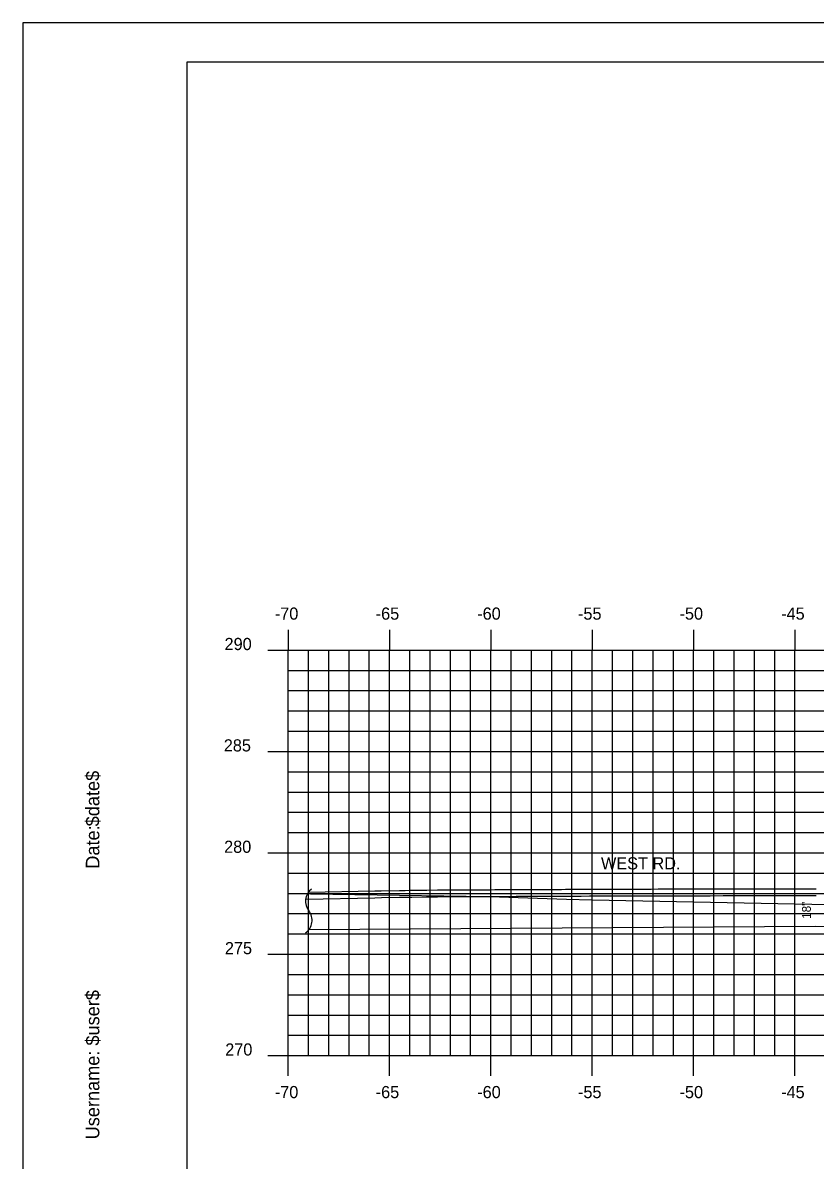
# Model space of a CAD drawing. Extents: x 853563 to 853733, y 366268 to 366378.
# Drawn here: x 853562.7 to 853601.8, y 366322.1 to 366378.2 of the extents above; entities that cross this region are included whole.
import ezdxf

# ---------------------------------------------------------------- set-up
doc = ezdxf.new("R2010")
doc.units = 0
for name, color, linetype in [('ANNOTATION', 7, 'Continuous'), ('BORDER', 7, 'Continuous'), ('D_Roadway_Edge_TW', 7, 'Continuous'), ('D_Roadway_SubGrade', 7, 'Continuous'), ('D_Text_Standard', 7, 'Continuous'), ('H_V ANNOTATION', 7, 'Continuous'), ('MAJOR', 7, 'Continuous'), ('MINOR', 7, 'Continuous'), ('PLOT BOUNDARY', 7, 'Continuous'), ('S_Roadway_Centerline', 7, 'Continuous')]:
    doc.layers.add(name, color=color, linetype=linetype)

msp = doc.modelspace()

# ---------------------------------------------------------------- linework, layer by layer
at = {"layer": 'BORDER'}
for p, q in [((853730.768, 366376.236), (853570.768, 366376.236)), ((853570.768, 366376.236), (853570.768, 366271.236))]:
    msp.add_line(p, q, dxfattribs=at)
at = {"layer": 'D_Roadway_Edge_TW'}
for points in [[(853576.768, 366335.291), (853580.042, 366335.354), (853580.361, 366335.36), (853581.26, 366335.377), (853581.487, 366335.381), (853581.532, 366335.382), (853581.769, 366335.387), (853581.863, 366335.388), (853582.591, 366335.401), (853582.613, 366335.402), (853582.614, 366335.402), (853582.615, 366335.402), (853583.136, 366335.405), (853583.505, 366335.407), (853583.521, 366335.407), (853583.564, 366335.407), (853584.465, 366335.412), (853585.346, 366335.417), (853585.473, 366335.418), (853585.477, 366335.418), (853585.505, 366335.418), (853585.723, 366335.419), (853585.759, 366335.419), (853585.957, 366335.42), (853587.02, 366335.425), (853587.089, 366335.426), (853587.351, 366335.427), (853587.553, 366335.428), (853588.237, 366335.431), (853588.247, 366335.431), (853588.251, 366335.431), (853588.901, 366335.434), (853589.162, 366335.435), (853589.25, 366335.435), (853589.453, 366335.436), (853590.225, 366335.439), (853590.629, 366335.441), (853590.703, 366335.441), (853590.832, 366335.442), (853590.862, 366335.442), (853590.913, 366335.442), (853591.437, 366335.444), (853591.78, 366335.445), (853592.137, 366335.446), (853592.611, 366335.448), (853592.746, 366335.448), (853592.908, 366335.448), (853593.097, 366335.449), (853593.311, 366335.45), (853593.67, 366335.451), (853594.015, 366335.452), (853594.136, 366335.452), (853594.261, 366335.452), (853594.711, 366335.454), (853595.103, 366335.454), (853595.433, 366335.455), (853595.691, 366335.455), (853595.766, 366335.455), (853595.868, 366335.455), (853596.045, 366335.455), (853596.172, 366335.455), (853596.59, 366335.455), (853597.224, 366335.457), (853597.358, 366335.457), (853597.436, 366335.457), (853597.634, 366335.457), (853597.987, 366335.457), (853598.168, 366335.458), (853598.26, 366335.458), (853598.744, 366335.459), (853598.97, 366335.458), (853599.067, 366335.458), (853599.282, 366335.459), (853599.953, 366335.46), (853600.212, 366335.459), (853600.27, 366335.459), (853600.291, 366335.459), (853600.34, 366335.459), (853600.474, 366335.46), (853601.089, 366335.46), (853601.288, 366335.46), (853601.69, 366335.461), (853601.808, 366335.46)], [(853576.632, 366334.955), (853580.049, 366335.021), (853580.367, 366335.027), (853581.267, 366335.044), (853581.493, 366335.048), (853581.539, 366335.049), (853581.775, 366335.054), (853581.869, 366335.055), (853582.595, 366335.068), (853582.615, 366335.069), (853582.616, 366335.069), (853582.616, 366335.069), (853583.138, 366335.072), (853583.507, 366335.074), (853583.523, 366335.074), (853583.566, 366335.074), (853584.467, 366335.079), (853585.348, 366335.084), (853585.474, 366335.085), (853585.479, 366335.085), (853585.724, 366335.086), (853585.761, 366335.086), (853585.958, 366335.087), (853587.022, 366335.092), (853587.09, 366335.093), (853587.352, 366335.094), (853587.555, 366335.095), (853588.238, 366335.098), (853588.249, 366335.098), (853588.252, 366335.098), (853588.903, 366335.101), (853589.163, 366335.102), (853589.252, 366335.102), (853589.455, 366335.103), (853590.227, 366335.106), (853590.63, 366335.108), (853590.705, 366335.108), (853590.833, 366335.109), (853590.863, 366335.109), (853590.914, 366335.109), (853591.781, 366335.112), (853592.138, 366335.113), (853592.612, 366335.115), (853592.747, 366335.115), (853593.098, 366335.116), (853593.312, 366335.117), (853593.671, 366335.118), (853594.016, 366335.119), (853594.137, 366335.119), (853594.262, 366335.119), (853594.711, 366335.121), (853595.103, 366335.121), (853595.434, 366335.122), (853595.691, 366335.122), (853595.767, 366335.122), (853595.868, 366335.122), (853596.046, 366335.122), (853596.172, 366335.122), (853596.59, 366335.122), (853597.225, 366335.124), (853597.358, 366335.124), (853597.436, 366335.124), (853597.634, 366335.124), (853597.988, 366335.124), (853598.168, 366335.125), (853598.261, 366335.125), (853598.744, 366335.126), (853598.97, 366335.125), (853599.067, 366335.125), (853599.283, 366335.126), (853599.953, 366335.127), (853600.212, 366335.126), (853600.27, 366335.126), (853600.291, 366335.126), (853600.34, 366335.126), (853600.475, 366335.127), (853601.089, 366335.127), (853601.288, 366335.127), (853601.69, 366335.128), (853601.808, 366335.127)]]:
    msp.add_lwpolyline(points, dxfattribs=at)
for centre, start, end in [((853577.387, 366334.844), 127.9752, 217.9752), ((853576.183, 366333.904), 305.7646, 37.9752)]:
    msp.add_arc(centre, 0.764, start, end, dxfattribs=at)
at = {"layer": 'D_Roadway_SubGrade'}
msp.add_lwpolyline([(853576.803, 366333.458), (853601.768, 366333.627), (853626.771, 366333.22)], dxfattribs=at)
at = {"layer": 'MAJOR'}
for p, q in [((853575.768, 366348.238), (853575.768, 366347.236)), ((853580.768, 366348.238), (853580.768, 366347.236)), ((853585.768, 366348.238), (853585.768, 366347.236)), ((853590.768, 366348.238), (853590.768, 366347.236)), ((853595.768, 366348.238), (853595.768, 366347.236)), ((853600.768, 366348.238), (853600.768, 366347.236)), ((853574.766, 366347.236), (853575.768, 366347.236)), ((853575.768, 366347.236), (853715.768, 366347.236)), ((853575.768, 366327.236), (853575.768, 366347.236)), ((853575.768, 366327.236), (853575.768, 366347.236)), ((853575.768, 366347.236), (853715.768, 366347.236)), ((853580.768, 366327.236), (853580.768, 366347.236)), ((853585.768, 366327.236), (853585.768, 366347.236)), ((853590.768, 366327.236), (853590.768, 366347.236)), ((853595.768, 366327.236), (853595.768, 366347.236)), ((853600.768, 366327.236), (853600.768, 366347.236)), ((853574.766, 366342.236), (853575.768, 366342.236)), ((853575.768, 366342.236), (853715.768, 366342.236)), ((853574.766, 366337.236), (853575.768, 366337.236)), ((853575.768, 366337.236), (853715.768, 366337.236)), ((853574.766, 366332.236), (853575.768, 366332.236)), ((853575.768, 366332.236), (853715.768, 366332.236)), ((853574.766, 366327.236), (853575.768, 366327.236)), ((853575.768, 366327.236), (853715.768, 366327.236)), ((853575.768, 366327.236), (853715.768, 366327.236)), ((853575.768, 366326.234), (853575.768, 366327.236)), ((853580.768, 366326.234), (853580.768, 366327.236)), ((853585.768, 366326.234), (853585.768, 366327.236)), ((853590.768, 366326.234), (853590.768, 366327.236)), ((853595.768, 366326.234), (853595.768, 366327.236)), ((853600.768, 366326.234), (853600.768, 366327.236))]:
    msp.add_line(p, q, dxfattribs=at)
at = {"layer": 'MINOR'}
for p, q in [((853576.768, 366327.236), (853576.768, 366347.236)), ((853577.768, 366327.236), (853577.768, 366347.236)), ((853578.768, 366327.236), (853578.768, 366347.236)), ((853579.768, 366327.236), (853579.768, 366347.236)), ((853581.768, 366327.236), (853581.768, 366347.236)), ((853582.768, 366327.236), (853582.768, 366347.236)), ((853583.768, 366327.236), (853583.768, 366347.236)), ((853584.768, 366327.236), (853584.768, 366347.236)), ((853586.768, 366327.236), (853586.768, 366347.236)), ((853587.768, 366327.236), (853587.768, 366347.236)), ((853588.768, 366327.236), (853588.768, 366347.236)), ((853589.768, 366327.236), (853589.768, 366347.236)), ((853591.768, 366327.236), (853591.768, 366347.236)), ((853592.768, 366327.236), (853592.768, 366347.236)), ((853593.768, 366327.236), (853593.768, 366347.236)), ((853594.768, 366327.236), (853594.768, 366347.236)), ((853596.768, 366327.236), (853596.768, 366347.236)), ((853597.768, 366327.236), (853597.768, 366347.236)), ((853598.768, 366327.236), (853598.768, 366347.236)), ((853599.768, 366327.236), (853599.768, 366347.236)), ((853575.768, 366346.236), (853715.768, 366346.236)), ((853575.768, 366346.236), (853576.77, 366346.236)), ((853575.768, 366345.236), (853715.768, 366345.236)), ((853575.768, 366345.236), (853576.77, 366345.236)), ((853575.768, 366344.236), (853715.768, 366344.236)), ((853575.768, 366344.236), (853576.77, 366344.236)), ((853575.768, 366343.236), (853715.768, 366343.236)), ((853575.768, 366343.236), (853576.77, 366343.236)), ((853575.768, 366341.236), (853715.768, 366341.236)), ((853575.768, 366341.236), (853576.77, 366341.236)), ((853575.768, 366340.236), (853715.768, 366340.236)), ((853575.768, 366340.236), (853576.77, 366340.236)), ((853575.768, 366339.236), (853715.768, 366339.236)), ((853575.768, 366339.236), (853576.77, 366339.236)), ((853575.768, 366338.236), (853715.768, 366338.236)), ((853575.768, 366338.236), (853576.77, 366338.236)), ((853575.768, 366336.236), (853715.768, 366336.236)), ((853575.768, 366336.236), (853576.77, 366336.236)), ((853575.768, 366335.236), (853715.768, 366335.236)), ((853575.768, 366335.236), (853576.77, 366335.236)), ((853575.768, 366334.236), (853715.768, 366334.236)), ((853575.768, 366334.236), (853576.77, 366334.236)), ((853575.768, 366333.236), (853715.768, 366333.236)), ((853575.768, 366333.236), (853576.77, 366333.236)), ((853575.768, 366331.236), (853715.768, 366331.236)), ((853575.768, 366331.236), (853576.77, 366331.236)), ((853575.768, 366330.236), (853715.768, 366330.236)), ((853575.768, 366330.236), (853576.77, 366330.236)), ((853575.768, 366329.236), (853715.768, 366329.236)), ((853575.768, 366329.236), (853576.77, 366329.236)), ((853575.768, 366328.236), (853715.768, 366328.236)), ((853575.768, 366328.236), (853576.77, 366328.236))]:
    msp.add_line(p, q, dxfattribs=at)
at = {"layer": 'PLOT BOUNDARY'}
msp.add_lwpolyline([(853562.674, 366268.177), (853732.674, 366268.177), (853732.674, 366378.177), (853562.674, 366378.177)], close=True, dxfattribs=at)
at = {"layer": 'S_Roadway_Centerline'}
msp.add_lwpolyline([(853575.768, 366335.23), (853584.553, 366335.101), (853586.197, 366335.061), (853587.12, 366335.034), (853589.489, 366334.954), (853590.768, 366334.911), (853605.767, 366334.615)], dxfattribs=at)

# ---------------------------------------------------------------- texts
at = {"layer": 'ANNOTATION'}
msp.add_text('WEST RD.', height=0.6, dxfattribs=at).set_placement((853591.198, 366336.418))
at = {"layer": 'BORDER'}
for s, p in [('$date$', (853566.453, 366338.542)), ('Date:', (853566.453, 366336.453)), ('$user$', (853566.453, 366327.728)), ('Username:', (853566.453, 366323.104))]:
    msp.add_text(s, height=0.6696, rotation=90, dxfattribs=at).set_placement(p)
at = {"layer": 'D_Text_Standard'}
msp.add_text('18"', height=0.4335, rotation=90, dxfattribs=at).set_placement((853601.55, 366333.977))
at = {"layer": 'H_V ANNOTATION'}
for s, p in [('-70', (853575.109, 366348.736)), ('-65', (853580.085, 366348.736)), ('-60', (853585.093, 366348.736)), ('-55', (853590.064, 366348.736)), ('-50', (853595.072, 366348.736)), ('-45', (853600.085, 366348.736)), ('290', (853572.63, 366347.236)), ('285', (853572.592, 366342.236)), ('280', (853572.608, 366337.236)), ('275', (853572.646, 366332.236)), ('270', (853572.662, 366327.236)), ('-70', (853575.109, 366325.136)), ('-65', (853580.085, 366325.136)), ('-60', (853585.093, 366325.136)), ('-55', (853590.064, 366325.136)), ('-50', (853595.072, 366325.136)), ('-45', (853600.085, 366325.136))]:
    msp.add_text(s, height=0.6, dxfattribs=at).set_placement(p)
at = {"layer": 'MAJOR'}
msp.add_text('-', height=0.00000006, rotation=53.1301, dxfattribs=at).set_placement((853575.763, 366327.236))

doc.saveas('drawing.dxf')
